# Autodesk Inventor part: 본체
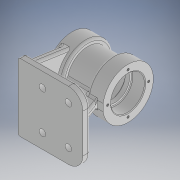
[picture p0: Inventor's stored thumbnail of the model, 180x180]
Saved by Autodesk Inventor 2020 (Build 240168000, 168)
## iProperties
Created: 2024-02
Part Number: 본체
Material: 일반
Document SubType Name: Modeling
Designer: oem
Density: 1 g/cm^3
Appearance: 기본값
Author: oem
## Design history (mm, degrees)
sketch "스케치1"
  geometry: C1 r 28.5 at (0, 0); 1 further point
  constraints: 1 centre point, 1 coincident
  dimensions: "d0" = 57 diameter of C1
extrude "돌출1" new body sketch "스케치1" distance "d1" = 78; taper "d2" = 0 deg
node "작업 평면1"
sketch "스케치4"
  geometry: L1 (78, -28.5)-(78, 28.5) reference; L2 (0, -28.5)-(0, 28.5) reference; L3 (0, 0)-(78, 0); L4 (5, -47)-(95, -47); L5 (95, -47)-(95, 47); L6 (95, 47)-(5, 47); L7 (5, 47)-(5, -47)
  constraints: 10 end point, 2 parallel, 1 horizontal, 1 midpoint, 1 perpendicular
  dimensions: "d22" = 5 distance between parallel lines of L7 L2; "d23" = 90 distance between parallel lines of L5 L7; "d24" = 94 distance between parallel lines of L6 L4; "d25" = 47 distance between parallel lines of L3 L4
extrude "돌출2" join sketch "스케치4" distance "d26" = 10; taper "d27" = 0 deg
sketch "스케치5"
  geometry: L1 (-10, 0)-(-10, 94) reference; L2 (-10, 8)-(-84.109, 18.798); L3 (-10, 94)-(-10, 0) reference; L4 (-10, 86)-(-84.109, 75.202); A1 r 28.5 centre (-80, 47) between (-84.109, 75.202) and (-84.109, 18.798) reference; 2 further points
  constraints: 4 end point, 2 point on circle, 2 point on line, 2 tangent
  dimensions: "d28" = 8 distance of L2.start L1.start; "d29" = 8 distance of L4.start L1.end
extrude "돌출3" join sketch "스케치5" distance "d30" = 10; taper "d31" = 0 deg
sketch "스케치7"
  geometry: L1 (-5, 47)-(-5, -47) reference; C1 r 10 at (-39, -27); C2 r 10 at (-75, -27); C3 r 10 at (-75, 27); C4 r 10 at (-39, 27); 1 further point
  constraints: 4 centre point
  dimensions: "d38" = 20 diameter of C1; "d39" = 20 diameter of C2; "d40" = 20 diameter of C3; "d41" = 20 diameter of C4; "d42" = 34 distance from line of C1.centre L1; "d43" = 34 distance from line of L1 C4.centre; "d44" = 36 distance of C2.centre C1.centre; "d45" = 36 distance of C3.centre C4.centre; "d46" = 27 vertical distance of point (0, 0) C1.centre; "d47" = 27 vertical distance of point (0, 0) C4.centre; "d48" = 27 vertical distance of point (0, 0) C2.centre; "d49" = 27 vertical distance of point (0, 0) C3.centre
extrude "돌출5" join sketch "스케치7" distance "d50" = 3; taper "d51" = 0 deg
sketch "스케치8"
  geometry: C1 r 10 at (0, 0) reference; C2 r 4.5 at (0, 0); C3 r 10 at (36, 0) reference; C4 r 4.5 at (36, 0); C5 r 10 at (36, -54) reference; C6 r 4.5 at (36, -54); C7 r 10 at (0, -54) reference; C8 r 4.5 at (0, -54); 1 further point
  constraints: 4 centre point, 4 coincident
  dimensions: "d52" = 9 diameter of C2; "d53" = 9 diameter of C4; "d54" = 9 diameter of C6; "d55" = 9 diameter of C8
extrude "돌출6" cut sketch "스케치8" extent not by distance; stored distance "d56" = 89.271; taper "d57" = 0 deg
sketch "스케치12"
  geometry: C1 r 28.5 at (0, 0) reference; C2 r 35 at (0, 0)
  constraints: 1 centre point, 1 coincident
  dimensions: "d82" = 70 diameter of C2
extrude "돌출9" join sketch "스케치12" distance "d83" = 22; taper "d84" = 0 deg
sketch "스케치14"
  geometry: C1 r 28.5 at (0, 0) reference; C2 r 35 at (0, 0)
  constraints: 1 centre point, 1 coincident
  dimensions: "d88" = 70 diameter of C2
extrude "돌출11" join sketch "스케치14" distance "d89" = 22; taper "d90" = 0 deg
node "작업 평면2"
node "작업 평면3"
sketch "스케치18"
  geometry: L1 (0, 35)-(0, -35) reference; C1 r 6 at (39, 0); 1 further point
  constraints: 1 centre point
  dimensions: "d107" = 12 diameter of C1; "d108" = 39 distance from line of C1.centre L1
extrude "돌출14" join sketch "스케치18" stored distance "d109" = 3; taper "d110" = 0 deg
sketch "스케치19"
  geometry: C1 r 6 at (0, 0) reference; C2 r 3.5 at (0, 0); 1 further point
  constraints: 1 centre point, 1 coincident
  dimensions: "d111" = 7 diameter of C2
extrude "돌출15" cut sketch "스케치19" distance "d112" = 2; taper "d113" = 0 deg
sketch "스케치17"
  geometry: L1 (-78, 35)-(-78, -35) reference; L2 (-18, 0)-(-18, -22.5); L3 (-17, -23.5)-(0, -23.5); L4 (0, -23.5)-(0, 0); L5 (-18, 0)-(-24, 0); L6 (-24, 0)-(-24, -20); L7 (-24, -20)-(-18, -20); L8 (-18, -20)-(-18, 0); L9 (-24, 0)-(-54, 0); L10 (-54, 0)-(-54, -20.5); L11 (-51, -23.5)-(-27, -23.5); L12 (-24, -20.5)-(-24, 0); L13 (-54, 0)-(-60, 0); L14 (-60, 0)-(-60, -20); L15 (-60, -20)-(-54, -20); L16 (-54, -20)-(-54, 0); L17 (-60, 0)-(-78, 0); L18 (-78, 0)-(-78, -23.5); L19 (-78, -23.5)-(-61, -23.5); L20 (-60, -22.5)-(-60, 0); L21 (0, 0)-(-18, 0); L22 (0, -35)-(0, 35) reference; A1 r 1 centre (-17, -22.5) between (-18, -22.5) and (-17, -23.5); A2 r 1 centre (-61, -22.5) between (-61, -23.5) and (-60, -22.5); A3 r 3 centre (-27, -20.5) between (-27, -23.5) and (-24, -20.5); A4 r 3 centre (-51, -20.5) between (-54, -20.5) and (-51, -23.5); 9 further points
  constraints: 40 end point, 12 point on line, 9 parallel, 8 point on circle, 8 tangent, 5 perpendicular, 4 centre point, 4 horizontal, 2 equal radius
  dimensions: "d99" = 18 distance of L3.end point (-18, -23.5); "d100" = 30 distance of point (-24, -23.5) point (-54, -23.5); "d101" = 18 distance of L18.end point (-60, -23.5); "d102" = 6 distance between parallel lines of L6 L8; "d103" = 47 diameter of L3 L21; "d104" = 40 diameter of L7 L5; "d129" = 1 radius of A1; "d130" = 3 radius of A3
revolve "회전1" sketch "스케치17" stored, may be unused: angle "d105" = 90 deg
sketch "스케치20"
  geometry: C1 r 6 at (0, 0) reference; 2 further points
  constraints: 1 coincident
hole "구멍4" sketch "스케치20" at (0, 0) diameter "d114" = 4.917; stored, may be unused: countersink angle "d118" = 90 deg, drill point angle "d120" = 118 deg; dims "d115" = 12, "d116" = 4, "d117" = 2, "d119" = 17.1
chamfer "모따기1" distance "d131" = 1; stored, may be unused: second distance "d132" = 2, angle "d133" = 45 deg
fillet "모깎기15" dims "d139" = 3
fillet "모깎기16" dims "d140" = 3
fillet "모깎기17" dims "d141" = 3
fillet "모깎기18" dims "d142" = 3
fillet "모깎기19" dims "d143" = 3
fillet "모깎기22" dims "d154" = 20
fillet "모깎기23" dims "d155" = 3
sketch "스케치27"
  geometry: L1 (-5, 44)-(-5, -44) reference; L2 (-5, -5)-(-83, -5); L3 (-83, -5)-(-83, 5); L4 (-83, 5)-(-5, 5); L5 (-5, 5)-(-5, -5); L6 (-95, 27)-(-95, -27) reference; 2 further points
  constraints: 8 end point, 2 parallel, 1 horizontal, 1 perpendicular, 1 point on line
  dimensions: "d175" = 12 distance between parallel lines of L3 L6; "d176" = 5 distance from line of point (0, 0) L2; "d177" = 10 distance between parallel lines of L4 L2
extrude "돌출20" join sketch "스케치27" stored distance "d178" = 10; taper "d179" = 0 deg; dims "d29" = 8
sketch "스케치28"
  geometry: L1 (63, 35.359)-(63, 41.942) reference; L2 (44, 35.359)-(63, 35.359) reference; L3 (68, 0)-(0, 0) reference; L4 (68, 0)-(68, 41.942) reference; L5 (63, 41.942)-(68, 41.942) reference; L6 (68, 0)-(55.13, 35.359); 1 further point
  constraints: 2 end point, 1 point on line
  dimensions: "d180" = 70 deg angle of L3 L6
extrude "돌출21" cut sketch "스케치28" distance "d181" = 10; taper "d182" = 0 deg
fillet "모깎기24" dims "d183" = 3
fillet "모깎기25" dims "d184" = 3
fillet "모깎기26" dims "d185" = 3
fillet "모깎기27" dims "d186" = 3
fillet "모깎기28" dims "d187" = 3
sketch "스케치29" dims "d188" = 57
  geometry: C1 r 20.5 at (0, 0) reference; 2 further points
  constraints: 1 coincident, 1 horizontal alignment, 2 other
hole "구멍7" sketch "스케치29" at (-28.5, 0) diameter "d189" = 3.242; stored, may be unused: countersink angle "d193" = 90 deg, drill point angle "d195" = 118 deg; dims "d190" = 8, "d191" = 4, "d192" = 2, "d194" = 10
sketch "스케치30"
  geometry: C1 r 1.621 at (28.5, 0) reference; C2 r 1.621 at (0, 28.5) reference; C3 r 1.621 at (-28.5, 0) reference; C4 r 1.621 at (0, -28.5) reference
hole "구멍8" sketch "스케치30" at (0, -28.5), (28.5, 0), (0, 28.5), (-28.5, 0) diameter "d199" = 3.242; stored, may be unused: countersink angle "d203" = 90 deg, drill point angle "d205" = 118 deg; dims "d200" = 8, "d201" = 4, "d202" = 2, "d204" = 10
node "솔리드1"
pattern_circular "원형 패턴3" dims angle "d197" = 360 deg
node "투영된 루프1"
node "투영된 루프2"
feature "A9D066F2-1C7D-4E18-AEED-F7BC21143FA4" dims "d189" = 3.242, "d190" = 8, "d191" = 4, "d192" = 2, "d193" = 90 deg, "d194" = 10, "d195" = 118 deg
other parameters: "d91" = -25.5, "d106" = -31.5
